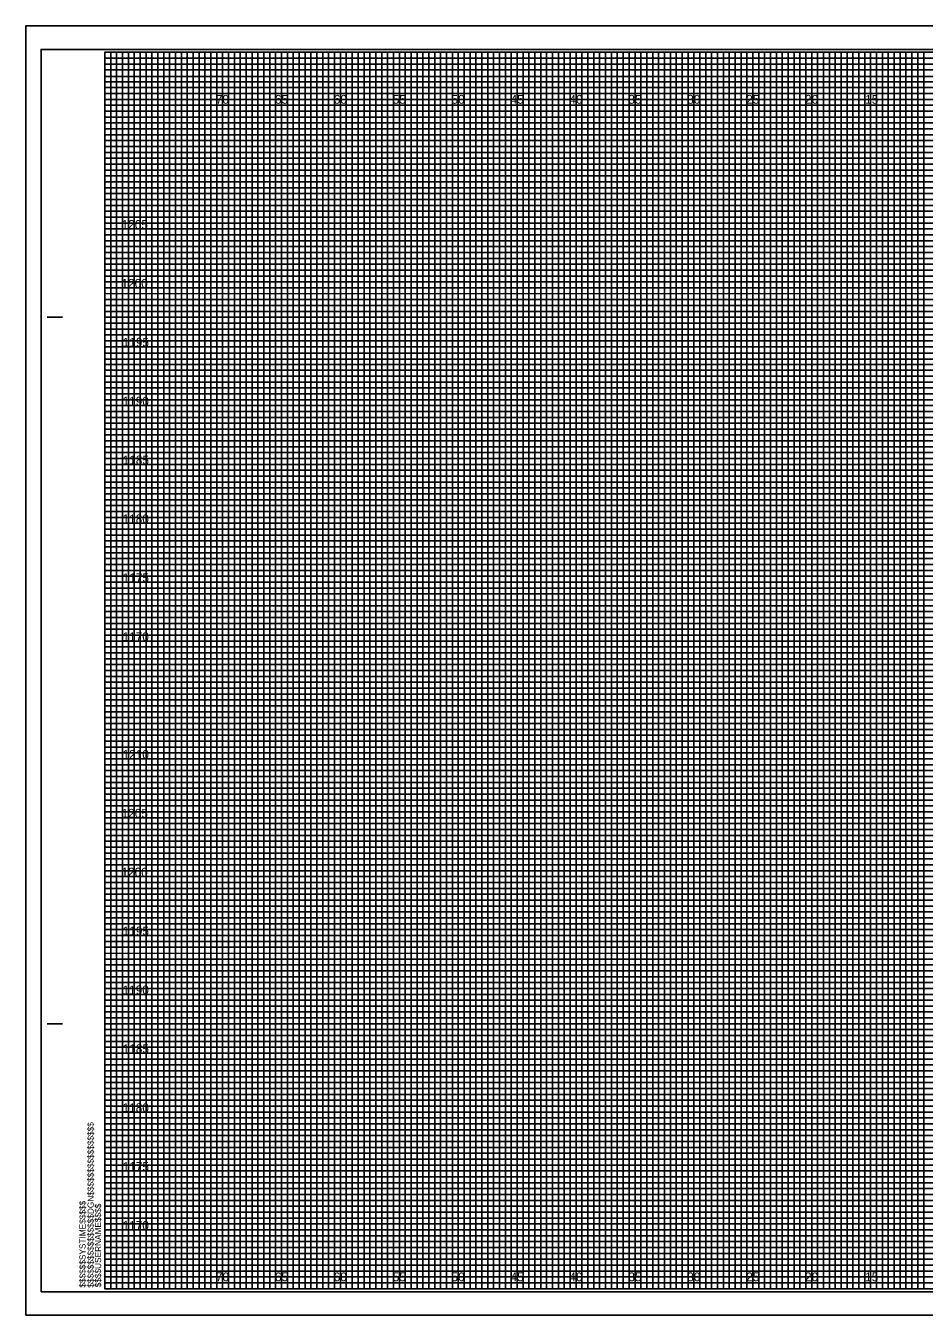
# Model space of a CAD drawing. Extents: x 3478 to 3647, y -9 to 1255.
# Drawn here: x 3478.3 to 3554.6, y 155.7 to 265.2 of the extents above; entities that cross this region are included whole.
import ezdxf

# ---------------------------------------------------------------- set-up
doc = ezdxf.new("R2010")
doc.units = 0
for name, color, linetype in [('Exist Cross Section Cell', 7, 'Continuous'), ('Prop CMT Subgrade Earthwork', 7, 'Continuous'), ('Prop Conc 4in Sidewalk', 7, 'Continuous'), ('Prop Conc Island Cover', 7, 'Continuous'), ('Sheet Cross Section CELL', 7, 'Continuous'), ('Sheet Cross Section Grid Minor 1 CELL', 7, 'Continuous'), ('Sheet Cross Section Grid Minor 2 CELL', 7, 'Continuous'), ('Sheet Cutting Line CELL', 7, 'Continuous'), ('Sheet DOT Grid CELL', 7, 'Continuous'), ('Sheet Plot Border Inside CELL', 7, 'Continuous')]:
    doc.layers.add(name, color=color, linetype=linetype)

msp = doc.modelspace()

# ---------------------------------------------------------------- linework, layer by layer
at = {"layer": 'Exist Cross Section Cell'}
for points in [[(3485.01, 262.97), (3487.51, 262.97), (3487.51, 157.97), (3492.51, 157.97), (3492.51, 262.97), (3497.51, 262.97), (3497.51, 157.97), (3502.51, 157.97), (3502.51, 262.97), (3507.51, 262.97), (3507.51, 157.97), (3512.51, 157.97), (3512.51, 262.97), (3517.51, 262.97), (3517.51, 157.97), (3522.51, 157.97), (3522.51, 262.97), (3527.51, 262.97), (3527.51, 157.97), (3532.51, 157.97), (3532.51, 262.97), (3537.51, 262.97), (3537.51, 157.97), (3542.51, 157.97), (3542.51, 262.97), (3547.51, 262.97), (3547.51, 157.97), (3552.51, 157.97), (3552.51, 262.97), (3557.51, 262.97)], [(3485.01, 260.47), (3622.51, 260.47)], [(3485.01, 250.47), (3645.01, 250.47), (3645.01, 255.47), (3485.01, 255.47)], [(3485.01, 240.47), (3645.01, 240.47), (3645.01, 245.47), (3485.01, 245.47)], [(3485.01, 230.47), (3645.01, 230.47), (3645.01, 235.47), (3485.01, 235.47)], [(3485.01, 220.47), (3645.01, 220.47), (3645.01, 225.47), (3485.01, 225.47)], [(3485.01, 210.47), (3645.01, 210.47), (3645.01, 215.47), (3485.01, 215.47)], [(3485.01, 200.47), (3645.01, 200.47), (3645.01, 205.47), (3485.01, 205.47)], [(3485.01, 190.47), (3645.01, 190.47), (3645.01, 195.47), (3485.01, 195.47)], [(3485.01, 180.47), (3645.01, 180.47), (3645.01, 185.47), (3485.01, 185.47)], [(3485.01, 170.47), (3645.01, 170.47), (3645.01, 175.47), (3485.01, 175.47)], [(3485.01, 160.47), (3645.01, 160.47), (3645.01, 165.47), (3485.01, 165.47)]]:
    msp.add_lwpolyline(points, dxfattribs=at)
at = {"layer": 'Prop CMT Subgrade Earthwork'}
msp.add_lwpolyline([(3478.31, 155.72), (3646.66, 155.72), (3646.66, 265.22), (3478.31, 265.22)], close=True, dxfattribs=at)
at = {"layer": 'Prop Conc 4in Sidewalk'}
for p, q in [((3490.01, 262.97), (3485.01, 262.97)), ((3490.01, 157.97), (3490.01, 262.97)), ((3500.01, 262.97), (3495.01, 262.97)), ((3495.01, 262.97), (3495.01, 157.97)), ((3500.01, 157.97), (3500.01, 262.97)), ((3510.01, 262.97), (3505.01, 262.97)), ((3505.01, 262.97), (3505.01, 157.97)), ((3510.01, 157.97), (3510.01, 262.97)), ((3520.01, 262.97), (3515.01, 262.97)), ((3515.01, 262.97), (3515.01, 157.97)), ((3520.01, 157.97), (3520.01, 262.97)), ((3530.01, 262.97), (3525.01, 262.97)), ((3525.01, 262.97), (3525.01, 157.97)), ((3530.01, 157.97), (3530.01, 262.97)), ((3540.01, 262.97), (3535.01, 262.97)), ((3535.01, 262.97), (3535.01, 157.97)), ((3540.01, 157.97), (3540.01, 262.97)), ((3550.01, 262.97), (3545.01, 262.97)), ((3545.01, 262.97), (3545.01, 157.97)), ((3550.01, 157.97), (3550.01, 262.97)), ((3495.01, 157.97), (3490.01, 157.97)), ((3505.01, 157.97), (3500.01, 157.97)), ((3515.01, 157.97), (3510.01, 157.97)), ((3525.01, 157.97), (3520.01, 157.97)), ((3535.01, 157.97), (3530.01, 157.97)), ((3545.01, 157.97), (3540.01, 157.97)), ((3555.01, 157.97), (3550.01, 157.97))]:
    msp.add_line(p, q, dxfattribs=at)
for points in [[(3485.01, 257.97), (3645.01, 257.97), (3645.01, 252.97), (3485.01, 252.97)], [(3485.01, 247.97), (3645.01, 247.97), (3645.01, 242.97), (3485.01, 242.97)], [(3485.01, 237.97), (3645.01, 237.97), (3645.01, 232.97), (3485.01, 232.97)], [(3485.01, 227.97), (3645.01, 227.97), (3645.01, 222.97), (3485.01, 222.97)], [(3485.01, 217.97), (3645.01, 217.97), (3645.01, 212.97), (3485.01, 212.97)], [(3485.01, 207.97), (3645.01, 207.97), (3645.01, 202.97), (3485.01, 202.97)], [(3485.01, 197.97), (3645.01, 197.97), (3645.01, 192.97), (3485.01, 192.97)], [(3485.01, 187.97), (3645.01, 187.97), (3645.01, 182.97), (3485.01, 182.97)], [(3485.01, 177.97), (3645.01, 177.97), (3645.01, 172.97), (3485.01, 172.97)], [(3485.01, 167.97), (3645.01, 167.97), (3645.01, 162.97), (3485.01, 162.97)]]:
    msp.add_lwpolyline(points, dxfattribs=at)
at = {"layer": 'Sheet Cross Section CELL'}
for p, q in [((3480.11, 240.47), (3481.36, 240.47)), ((3480.16, 240.47), (3481.41, 240.47)), ((3480.11, 180.47), (3481.36, 180.47)), ((3480.16, 180.47), (3481.41, 180.47))]:
    msp.add_line(p, q, dxfattribs=at)
msp.add_lwpolyline([(3645.01, 262.97), (3485.01, 262.97), (3485.01, 157.97), (3645.01, 157.97)], close=True, dxfattribs=at)
at = {"layer": 'Sheet Cross Section Grid Minor 1 CELL'}
for p, q in [((3485.01, 262.47), (3615.01, 262.47)), ((3615.01, 261.96), (3485.01, 261.96)), ((3485.01, 261.96), (3485.01, 261.47)), ((3485.01, 261.47), (3615.01, 261.47)), ((3615.01, 260.92), (3485.01, 260.92)), ((3485.01, 260.92), (3485.01, 259.97)), ((3485.01, 259.97), (3645.01, 259.97))]:
    msp.add_line(p, q, dxfattribs=at)
for points in [[(3485.01, 259.47), (3620.01, 259.47), (3645.01, 259.47), (3645.01, 258.97), (3485.01, 258.97)], [(3485.01, 258.47), (3645.01, 258.47), (3645.01, 257.47), (3485.01, 257.47)], [(3485.01, 256.97), (3645.01, 256.97), (3645.01, 256.47), (3485.01, 256.46)], [(3485.01, 255.97), (3645.01, 255.97), (3645.01, 254.97), (3485.01, 254.97)], [(3485.01, 254.47), (3645.01, 254.47), (3645.01, 253.97), (3485.01, 253.97)], [(3485.01, 253.47), (3645.01, 253.47), (3645.01, 252.47), (3485.01, 252.47)], [(3485.01, 251.97), (3645.01, 251.97), (3645.01, 251.47), (3485.01, 251.47)], [(3485.01, 250.97), (3645.01, 250.97), (3645.01, 249.97), (3485.01, 249.97)], [(3485.01, 249.47), (3645.01, 249.47), (3645.01, 248.97), (3485.01, 248.97)], [(3485.01, 248.47), (3645.01, 248.47), (3645.01, 247.47), (3485.01, 247.47)], [(3485.01, 246.97), (3645.01, 246.97), (3645.01, 246.47), (3485.01, 246.47)], [(3485.01, 245.97), (3645.01, 245.97), (3645.01, 244.95), (3645.01, 244.47), (3645.01, 243.97), (3485.01, 243.97)], [(3485.01, 244.97), (3645.01, 244.97), (3645.01, 244.47), (3485.01, 244.47)], [(3485.01, 243.47), (3645.01, 243.47), (3645.01, 242.47), (3485.01, 242.49)], [(3485.01, 242.49), (3645.01, 242.47), (3645.01, 241.97), (3485.01, 241.97)], [(3485.01, 241.47), (3645.01, 241.47), (3645.01, 240.97), (3485.01, 240.97)], [(3485.01, 239.97), (3645.01, 239.97), (3645.01, 239.47), (3485.01, 239.47)], [(3485.01, 238.97), (3645.01, 238.97), (3645.01, 238.47), (3485.01, 238.47)], [(3484.97, 237.42), (3645.01, 237.42), (3645.01, 236.91), (3484.97, 236.91)], [(3485.01, 236.47), (3645.01, 236.47), (3645.01, 235.97), (3485.01, 235.97)], [(3485.01, 234.97), (3645.01, 234.97), (3645.01, 234.47), (3485.01, 234.47)], [(3485.01, 233.97), (3645.01, 233.97), (3645.01, 233.47), (3485.01, 233.47)], [(3485.01, 232.47), (3645.01, 232.47), (3645.01, 231.97), (3485.01, 231.97)], [(3485.01, 231.47), (3645.01, 231.47), (3645.01, 230.97), (3485.01, 230.97)], [(3485.01, 229.97), (3645.01, 229.97), (3645.01, 229.47), (3485.01, 229.47)], [(3485.01, 228.97), (3645.01, 228.97), (3645.01, 228.47), (3485.01, 228.47)], [(3485.01, 227.47), (3645.01, 227.47), (3645, 226.96), (3485.01, 226.97)], [(3485.01, 226.47), (3645.01, 226.47), (3645.01, 225.97), (3485.01, 225.97)], [(3485.01, 224.97), (3645.01, 224.97), (3645.01, 224.47), (3485.01, 224.47)], [(3485.01, 223.97), (3645.01, 223.97), (3645.01, 223.47), (3485.01, 223.47)], [(3485.01, 222.47), (3645.01, 222.47), (3645.01, 221.97), (3485.01, 221.97)], [(3485.01, 221.47), (3645.01, 221.47), (3645.01, 220.97), (3485.01, 220.97)], [(3485.01, 219.97), (3645.01, 219.97), (3645.01, 219.47), (3485.01, 219.47)], [(3485.01, 218.97), (3645.01, 218.97), (3645.01, 218.47), (3485.01, 218.47)], [(3485.01, 217.47), (3645.01, 217.47), (3645.01, 216.97), (3485.01, 216.97)], [(3485.01, 216.47), (3645.04, 216.43), (3645.01, 215.97), (3485.01, 215.97)], [(3485.01, 214.97), (3645.01, 214.97), (3645.01, 214.47), (3485.01, 214.47)], [(3485.01, 213.97), (3645.01, 213.97), (3645.01, 213.47), (3485.01, 213.47)], [(3485.01, 212.47), (3645.01, 212.47), (3645.01, 211.97), (3485.01, 211.97)], [(3485.01, 211.47), (3645.01, 211.47), (3645.01, 210.97), (3485.01, 210.97)], [(3485.01, 209.97), (3645.01, 209.97), (3645.01, 209.47), (3485.01, 209.47)], [(3485.01, 208.97), (3645.01, 208.97), (3645.01, 208.47), (3485.01, 208.47)], [(3485.01, 207.47), (3645.01, 207.47), (3645.01, 206.97), (3485.01, 206.97)], [(3485.01, 206.47), (3645.01, 206.47), (3645.01, 205.97), (3485.01, 205.97)], [(3485.01, 204.97), (3645.01, 204.97), (3645.01, 204.47), (3485.01, 204.47)], [(3485.01, 203.97), (3645.01, 203.97), (3645.01, 203.47), (3485.01, 203.47)], [(3485.01, 202.47), (3645.01, 202.47), (3645.01, 201.97), (3485.01, 201.97)], [(3485.01, 201.47), (3645.01, 201.47), (3645.01, 200.97), (3485.01, 200.97)], [(3485.01, 199.97), (3645.01, 199.97), (3645.01, 199.47), (3485.01, 199.47)], [(3485.01, 198.97), (3645.01, 198.97), (3645.01, 198.47), (3485.01, 198.47)], [(3485.01, 197.47), (3645.01, 197.47), (3645, 196.96), (3485.01, 196.97)], [(3485.01, 196.47), (3645.01, 196.47), (3645.01, 195.97), (3485.01, 195.97)], [(3485.01, 194.97), (3645.01, 194.97), (3645.01, 194.47), (3485.01, 194.47)], [(3485.01, 193.97), (3645.01, 193.97), (3645.01, 193.47), (3485.01, 193.47)], [(3485.01, 192.47), (3645.01, 192.47), (3645.01, 191.97), (3485.01, 191.97)], [(3485.01, 191.47), (3645.01, 191.47), (3645.01, 190.97), (3485.01, 190.97)], [(3485.01, 189.97), (3645.01, 189.97), (3645.01, 189.47), (3485.01, 189.47)], [(3485.01, 188.97), (3645.01, 188.97), (3645.01, 188.47), (3485.01, 188.47)], [(3485.01, 187.47), (3645.01, 187.47), (3645.01, 186.97), (3485.01, 186.97)], [(3485.01, 186.47), (3645.04, 186.43), (3645.01, 185.97), (3485.01, 185.97)], [(3485.01, 184.97), (3645.01, 184.97), (3645.01, 184.47), (3485.01, 184.47)], [(3485.01, 183.97), (3645.01, 183.97), (3645.01, 183.47), (3485.01, 183.47)], [(3485.01, 182.47), (3645.01, 182.47), (3645.01, 181.97), (3485.01, 181.97)], [(3485.01, 181.47), (3645.01, 181.47), (3645.01, 180.97), (3485.01, 180.97)], [(3485.01, 179.97), (3645.01, 179.97), (3645.01, 179.47), (3485.01, 179.47)], [(3485.01, 178.97), (3645.01, 178.97), (3645.01, 178.47), (3485.01, 178.47)], [(3485.01, 177.47), (3645.01, 177.47), (3645.01, 176.97), (3485.01, 176.97)], [(3485.01, 176.47), (3645.01, 176.47), (3645.01, 175.97), (3485.01, 175.97)], [(3485.01, 174.97), (3645.01, 174.97), (3645.01, 174.47), (3485.01, 174.47)], [(3485.01, 173.97), (3645.01, 173.97), (3645.01, 173.47), (3485.01, 173.47)], [(3485.01, 172.47), (3645.01, 172.47), (3645.01, 171.97), (3485.01, 171.97)], [(3485.01, 171.47), (3645.01, 171.47), (3645.01, 170.97), (3485.01, 170.97)], [(3485.01, 169.97), (3645.01, 169.97), (3645.01, 169.47), (3485.01, 169.47)], [(3485.01, 168.97), (3645.01, 168.97), (3645.01, 168.47), (3485.01, 168.47)], [(3485.01, 167.47), (3645.01, 167.47), (3645.01, 166.97), (3485.01, 166.97)], [(3485.01, 166.47), (3645.01, 166.47), (3645.01, 165.97), (3485.01, 165.97)], [(3485.01, 164.97), (3645.01, 164.97), (3645.01, 164.47), (3485.01, 164.47)], [(3485.01, 163.97), (3645.01, 163.97), (3645.01, 163.47), (3485.01, 163.47)], [(3485.01, 162.47), (3645.01, 162.47), (3645.01, 161.97), (3485.01, 161.97)], [(3485.01, 161.47), (3645.01, 161.47), (3645.01, 160.97), (3485.01, 160.97)], [(3485.01, 159.97), (3645.01, 159.97), (3645.01, 159.47), (3485.01, 159.47)], [(3485.01, 158.97), (3645.01, 158.97), (3645.01, 158.47), (3485.01, 158.47)]]:
    msp.add_lwpolyline(points, dxfattribs=at)
at = {"layer": 'Sheet Cross Section Grid Minor 2 CELL'}
for points in [[(3485.01, 157.97), (3485.51, 157.97), (3485.51, 262.97), (3486.01, 262.97), (3486.01, 157.97)], [(3486.01, 157.97), (3486.51, 157.97), (3486.51, 262.97), (3487.01, 262.97), (3487.01, 157.97)], [(3487.51, 157.97), (3488.01, 157.97), (3488.01, 262.97), (3488.51, 262.97), (3488.51, 157.97)], [(3488.51, 157.97), (3489.01, 157.97), (3489.01, 262.97), (3489.51, 262.97), (3489.51, 157.97)], [(3490.01, 157.97), (3490.51, 157.97), (3490.51, 262.97), (3491.01, 262.97), (3491.01, 157.97)], [(3491.01, 157.97), (3491.51, 157.97), (3491.51, 262.97), (3492.01, 262.97), (3492.01, 157.97)], [(3492.51, 157.97), (3493.01, 157.97), (3493.01, 262.97), (3493.51, 262.97), (3493.51, 157.97)], [(3493.51, 157.97), (3494.01, 157.97), (3494.01, 262.97), (3494.51, 262.97), (3494.51, 157.97)], [(3495.01, 157.97), (3495.51, 157.97), (3495.51, 262.97), (3496.01, 262.97), (3496.01, 157.97)], [(3496.01, 157.97), (3496.51, 157.97), (3496.51, 262.97), (3497.01, 262.97), (3497.01, 157.97)], [(3497.51, 157.97), (3498.01, 157.97), (3498.01, 262.97), (3498.51, 262.97), (3498.51, 157.97)], [(3498.51, 157.97), (3499.01, 157.97), (3499.01, 262.97), (3499.51, 262.97), (3499.51, 157.97)], [(3500.01, 157.97), (3500.51, 157.97), (3500.51, 262.97), (3501.01, 262.97), (3501.01, 157.97)], [(3501.01, 157.97), (3501.51, 157.97), (3501.51, 262.97), (3502.01, 262.97), (3502.01, 157.97)], [(3502.51, 157.97), (3503.01, 157.97), (3503.01, 262.97), (3503.51, 262.97), (3503.51, 157.97)], [(3503.51, 157.97), (3504.01, 157.97), (3504.01, 262.97), (3504.51, 262.97), (3504.51, 157.97)], [(3505.01, 157.97), (3505.51, 157.97), (3505.51, 262.97), (3506.01, 262.97), (3506.01, 157.97)], [(3506.01, 157.97), (3506.51, 157.97), (3506.51, 262.97), (3507.01, 262.97), (3507.01, 157.97)], [(3507.51, 157.97), (3508.01, 157.97), (3508.01, 262.97), (3508.51, 262.97), (3508.51, 157.97)], [(3508.51, 157.97), (3509.01, 157.97), (3509.01, 262.97), (3509.51, 262.97), (3509.51, 157.97)], [(3510.01, 157.97), (3510.51, 157.97), (3510.51, 262.97), (3511.01, 262.97), (3511.01, 157.97)], [(3511.01, 157.97), (3511.51, 157.97), (3511.51, 262.97), (3512.01, 262.97), (3512.01, 157.97)], [(3512.51, 157.97), (3513.01, 157.97), (3513.01, 262.97), (3513.51, 262.97), (3513.51, 157.97)], [(3513.51, 157.97), (3514.01, 157.97), (3514.01, 262.97), (3514.51, 262.97), (3514.51, 157.97)], [(3515.01, 157.97), (3515.51, 157.97), (3515.51, 262.97), (3516.01, 262.97), (3516.01, 157.97)], [(3516.01, 157.97), (3516.51, 157.97), (3516.51, 262.97), (3517.01, 262.97), (3517.01, 157.97)], [(3517.51, 157.97), (3518.01, 157.97), (3518.01, 262.97), (3518.51, 262.97), (3518.51, 157.97)], [(3518.51, 157.97), (3519.01, 157.97), (3519.01, 262.97), (3519.51, 262.97), (3519.51, 157.97)], [(3520.01, 157.97), (3520.51, 157.97), (3520.51, 262.97), (3521.01, 262.97), (3521.01, 157.97)], [(3521.01, 157.97), (3521.51, 157.97), (3521.51, 262.97), (3522.01, 262.97), (3522.01, 157.97)], [(3522.51, 157.97), (3523.01, 157.97), (3523.01, 262.97), (3523.51, 262.97), (3523.51, 157.97)], [(3523.51, 157.97), (3524.01, 157.97), (3524.01, 262.97), (3524.51, 262.97), (3524.51, 157.97)], [(3525.01, 157.97), (3525.51, 157.97), (3525.51, 262.97), (3526.01, 262.97), (3526.01, 157.97)], [(3526.01, 157.97), (3526.51, 157.97), (3526.51, 262.97), (3527.01, 262.97), (3527.01, 157.97)], [(3527.51, 157.97), (3528.01, 157.97), (3528.01, 262.97), (3528.51, 262.97), (3528.51, 157.97)], [(3528.51, 157.97), (3529.01, 157.97), (3529.01, 262.97), (3529.51, 262.97), (3529.51, 157.97)], [(3530.01, 157.97), (3530.51, 157.97), (3530.51, 262.97), (3531.01, 262.97), (3531.01, 157.97)], [(3531.01, 157.97), (3531.51, 157.97), (3531.51, 262.97), (3532.01, 262.97), (3532.01, 157.97)], [(3532.51, 157.97), (3533.01, 157.97), (3533.01, 262.97), (3533.51, 262.97), (3533.51, 157.97)], [(3533.51, 157.97), (3534.01, 157.97), (3534.01, 262.97), (3534.51, 262.97), (3534.51, 157.97)], [(3535.01, 157.97), (3535.51, 157.97), (3535.51, 262.97), (3536.01, 262.97), (3536.01, 157.97)], [(3536.01, 157.97), (3536.51, 157.97), (3536.51, 262.97), (3537.01, 262.97), (3537.01, 157.97)], [(3537.51, 157.97), (3538.01, 157.97), (3538.01, 262.97), (3538.51, 262.97), (3538.51, 157.97)], [(3538.51, 157.97), (3539.01, 157.97), (3539.01, 262.97), (3539.51, 262.97), (3539.51, 157.97)], [(3540.01, 157.97), (3540.51, 157.97), (3540.51, 262.97), (3541.01, 262.97), (3541.01, 157.97)], [(3541.01, 157.97), (3541.51, 157.97), (3541.51, 262.97), (3542.01, 262.97), (3542.01, 157.97)], [(3542.51, 157.97), (3543.01, 157.97), (3543.01, 262.97), (3543.51, 262.97), (3543.51, 157.97)], [(3543.51, 157.97), (3544.01, 157.97), (3544.01, 262.97), (3544.51, 262.97), (3544.51, 157.97)], [(3545.01, 157.97), (3545.51, 157.97), (3545.51, 262.97), (3546.01, 262.97), (3546.01, 157.97)], [(3546.01, 157.97), (3546.51, 157.97), (3546.51, 262.97), (3547.01, 262.97), (3547.01, 157.97)], [(3547.51, 157.97), (3548.01, 157.97), (3548.01, 262.97), (3548.51, 262.97), (3548.51, 157.97)], [(3548.51, 157.97), (3549.01, 157.97), (3549.01, 262.97), (3549.51, 262.97), (3549.51, 157.97)], [(3550.01, 157.97), (3550.51, 157.97), (3550.51, 262.97), (3551.01, 262.97), (3551.01, 157.97)], [(3551.01, 157.97), (3551.51, 157.97), (3551.51, 262.97), (3552.01, 262.97), (3552.01, 157.97)], [(3552.51, 157.97), (3553.01, 157.97), (3553.01, 262.97), (3553.51, 262.97), (3553.51, 157.97)], [(3553.51, 157.97), (3554.01, 157.97), (3554.01, 262.97), (3554.51, 262.97), (3554.51, 157.97)]]:
    msp.add_lwpolyline(points, dxfattribs=at)
at = {"layer": 'Sheet Cutting Line CELL'}
for p, q in [((3646.66, 265.22), (3478.31, 265.22)), ((3478.31, 265.22), (3478.31, 155.72)), ((3478.31, 155.72), (3646.66, 155.72))]:
    msp.add_line(p, q, dxfattribs=at)
at = {"layer": 'Sheet DOT Grid CELL'}
for p, q in [((3490.01, 157.97), (3490.01, 262.97)), ((3495.01, 157.97), (3495.01, 262.97)), ((3500.01, 157.97), (3500.01, 262.97)), ((3505.01, 157.97), (3505.01, 262.97)), ((3510.01, 157.97), (3510.01, 262.97)), ((3515.01, 157.97), (3515.01, 262.97)), ((3520.01, 157.97), (3520.01, 262.97)), ((3525.01, 157.97), (3525.01, 262.97)), ((3530.01, 157.97), (3530.01, 262.97)), ((3535.01, 157.97), (3535.01, 262.97)), ((3540.01, 157.97), (3540.01, 262.97)), ((3545.01, 157.97), (3545.01, 262.97)), ((3550.01, 157.97), (3550.01, 262.97)), ((3485.01, 257.97), (3645.01, 257.97)), ((3485.01, 252.97), (3645.01, 252.97)), ((3485.01, 247.97), (3645.01, 247.97)), ((3485.01, 242.97), (3645.01, 242.97)), ((3485.01, 237.97), (3645.01, 237.97)), ((3485.01, 232.97), (3645.01, 232.97)), ((3485.01, 227.97), (3645.01, 227.97)), ((3485.01, 222.97), (3645.01, 222.97)), ((3485.01, 217.97), (3645.01, 217.97)), ((3485.01, 212.97), (3645.01, 212.97)), ((3485.01, 207.97), (3645.01, 207.97)), ((3485.01, 202.97), (3645.01, 202.97)), ((3485.01, 197.97), (3645.01, 197.97)), ((3485.01, 192.97), (3645.01, 192.97)), ((3485.01, 187.97), (3645.01, 187.97)), ((3485.01, 182.97), (3645.01, 182.97)), ((3485.01, 177.97), (3645.01, 177.97)), ((3485.01, 172.97), (3645.01, 172.97)), ((3485.01, 167.97), (3645.01, 167.97)), ((3485.01, 162.97), (3645.01, 162.97))]:
    msp.add_line(p, q, dxfattribs=at)
at = {"layer": 'Sheet Plot Border Inside CELL'}
msp.add_lwpolyline([(3479.61, 157.72), (3646.21, 157.72), (3646.21, 263.22), (3479.61, 263.22)], close=True, dxfattribs=at)

# ---------------------------------------------------------------- texts
at = {"layer": 'Prop Conc Island Cover'}
for s, p in [('70', (3494.44, 258.6)), ('65', (3499.45, 258.6)), ('60', (3504.44, 258.6)), ('55', (3509.45, 258.6)), ('50', (3514.44, 258.6)), ('45', (3519.45, 258.6)), ('40', (3524.44, 258.6)), ('35', (3529.45, 258.6)), ('30', (3534.44, 258.6)), ('25', (3539.45, 258.6)), ('20', (3544.44, 258.6)), ('15', (3549.54, 258.6)), ('1205', (3486.44, 247.97)), ('1200', (3486.43, 242.97)), ('1195', (3486.53, 237.97)), ('1190', (3486.52, 232.97)), ('1185', (3486.53, 227.97)), ('1180', (3486.52, 222.97)), ('1175', (3486.53, 217.97)), ('1170', (3486.52, 212.97)), ('1210', (3486.52, 202.97)), ('1205', (3486.44, 197.97)), ('1200', (3486.43, 192.97)), ('1195', (3486.53, 187.97)), ('1190', (3486.52, 182.97)), ('1185', (3486.53, 177.97)), ('1180', (3486.52, 172.97)), ('1175', (3486.53, 167.97)), ('1170', (3486.52, 162.97)), ('70', (3494.44, 158.6)), ('65', (3499.45, 158.6)), ('60', (3504.44, 158.6)), ('55', (3509.45, 158.6)), ('50', (3514.44, 158.6)), ('45', (3519.45, 158.6)), ('40', (3524.44, 158.6)), ('35', (3529.45, 158.6)), ('30', (3534.44, 158.6)), ('25', (3539.45, 158.6)), ('20', (3544.44, 158.6)), ('15', (3549.54, 158.6))]:
    msp.add_text(s, height=0.75, dxfattribs=at).set_placement(p)
at = {"layer": 'Sheet Cross Section CELL'}
for s, p in [('$$$$$$$$$$$$$$$$DGN$$$$$$$$$$$$$$$$', (3484.07, 158.06)), ('$$$$$$SYSTIME$$$$$', (3483.38, 158.06)), ('$$$$USERNAME$$$$', (3484.7, 158.09))]:
    msp.add_text(s, height=0.525, rotation=90, dxfattribs=at).set_placement(p)

doc.saveas('drawing.dxf')
